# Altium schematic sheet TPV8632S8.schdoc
size 127 x 101 mm
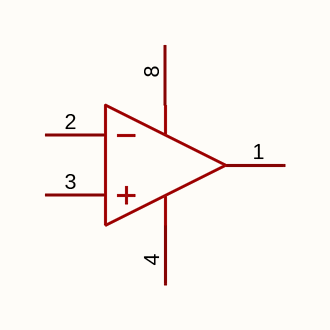
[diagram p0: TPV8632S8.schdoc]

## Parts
U?  tpv8632s8  [SOP-8_L4.9-W3.9-P1.27-LS6.0-BL]  (value not drawn)  (part A of 2)

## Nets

Not connected (* = marked no-connect by the designer): U? 1(OUTA) 2(INA-) 3(INA+) 4(VSS) 8(VDD)

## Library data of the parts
U? = tpv8632s8: 放大器数:2;轨到轨:轨到轨输入,轨到轨输出;增益带宽积(GBW):6MHz;输入失调电压(Vos):3.5mV;压摆率(SR):4.2V/us;输入偏置电流(Ib):1pA;; Manufacturer: TECH PUBLIC(台舟); AddInBom: yes; ModelId: 75c24a7891ee4dd6bdac16a7163ff87e; ModelName: SOP-8_L4.9-W3.9-P1.27-LS6.0-BL-1; ModelTransform: 192.913,236.22,0,0,0,0,-0.393,2.749,0; Number of Channels: 2; Maximum Power Supply Range (Vdd-Vss): 7.5V; Gain Bandwidth Product: 6MHz; Vos - Input Offset Voltage: 3.5mV; Input Offset Voltage Drift(Vos TC): 45uV/℃; Ib - Input Bias Current: 1pA; Input Voltage Noise Density: 9.5nV/√Hz@10kHz; Common Mode Rejection Ratio(CMRR): 97dB; Quiescent Current: 470uA; Output Current: 49mA; Single supply: 2.1V~5.5V; Dual Supply: -1.05V~2.75V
